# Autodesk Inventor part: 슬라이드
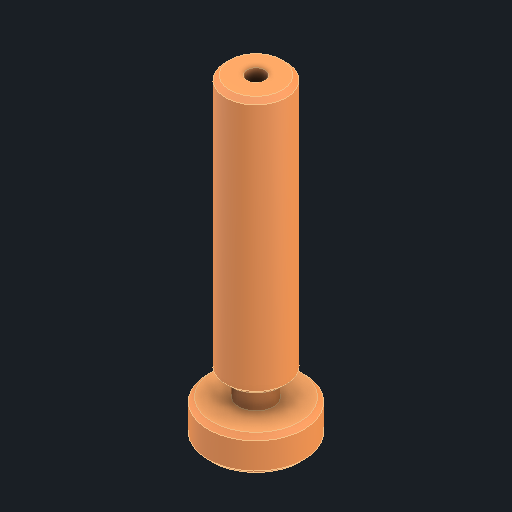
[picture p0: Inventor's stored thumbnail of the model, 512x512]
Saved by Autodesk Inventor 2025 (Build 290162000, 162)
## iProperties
Created: 2025-08
Part Number: 슬라이드
Material: 강철, 연강
Document SubType Name: Modeling
Designer: infra005
Density: 7.86 g/cm^3
Appearance: 기본값
Author: jhkim
Sending System: Autodesk Inventor 2026
Preprocessor: ST-DEVELOPER v20.1
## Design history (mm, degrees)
feature "솔리드1"
node "솔리드2"
